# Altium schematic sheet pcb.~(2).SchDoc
size A4; SheetNumber: 1; SheetTotal: 1
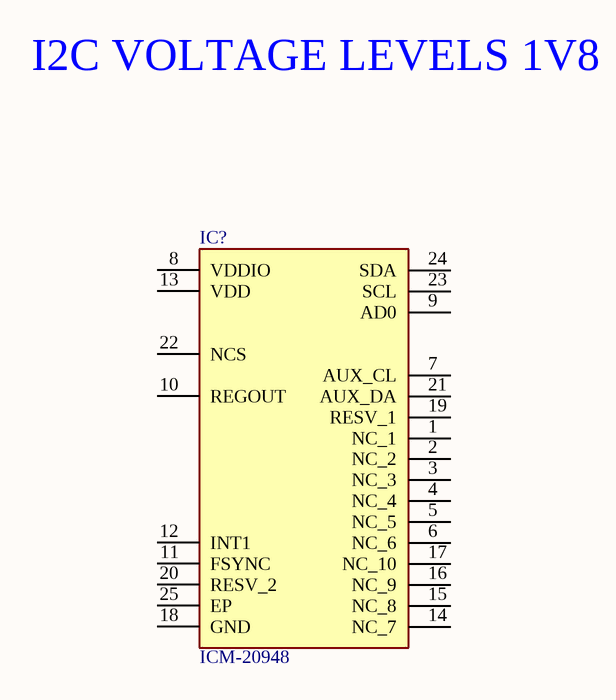
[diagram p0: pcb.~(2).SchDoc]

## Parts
IC?  ICM-20948  [QFN40P300X300X105-25N-D]

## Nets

Not connected (* = marked no-connect by the designer): IC? 1(NC_1) 2(NC_2) 3(NC_3) 4(NC_4) 5(NC_5) 6(NC_6) 7(AUX_CL) 8(VDDIO) 9(AD0) 10(REGOUT) 11(FSYNC) 12(INT1) 13(VDD) 14(NC_7) 15(NC_8) 16(NC_9) 17(NC_10) 18(GND) 19(RESV_1) 20(RESV_2) 21(AUX_DA) 22(NCS) 23(SCL) 24(SDA) 25(EP)

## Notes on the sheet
- I2C VOLTAGE LEVELS 1V8

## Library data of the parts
IC? = ICM-20948: Integrated Circuit; Manufacturer_Name: TDK; Description: IMUs - Inertial Measurement Units World's Lowest Power 9-Axis MEMS MotionTracking Device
